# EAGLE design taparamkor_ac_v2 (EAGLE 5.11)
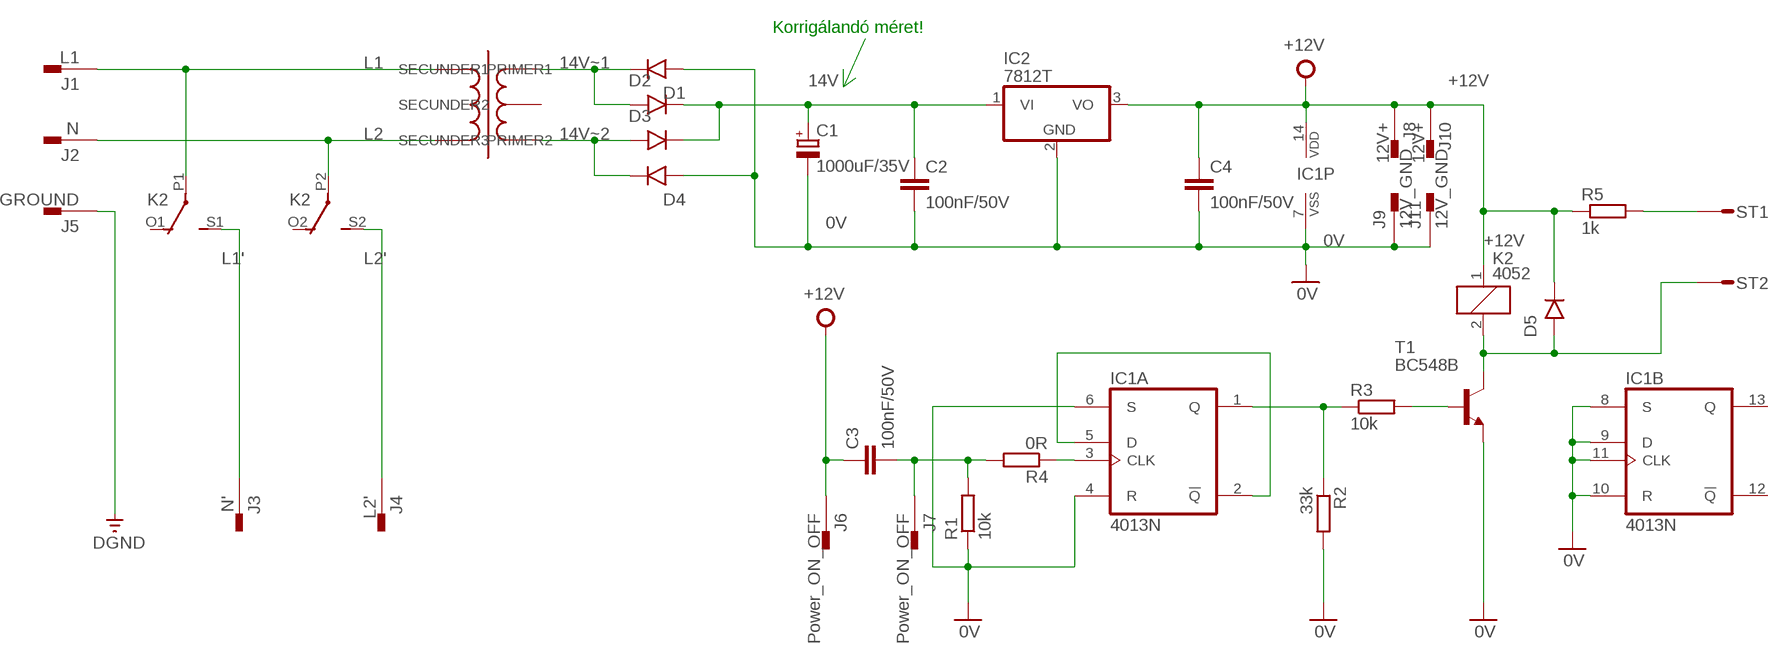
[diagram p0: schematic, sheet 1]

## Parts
C1  1000uF/35V  CPOL-EUE7.5-16  [E7,5-16]
C2  100nF/50V  C-EU025_050-025X075  [C025_050-025X075]
C3  100nF/50V  C-EU025_050-025X075  [C025_050-025X075]
C4  100nF/50V  C-EU025_050-025X075  [C025_050-025X075]
D1  1N4001  [DO41-10]
D2  1N4001  [DO41-10]
D3  1N4001  [DO41-10]
D4  1N4001  [DO41-10]
D5  1N4001  [DO41-10]
IC1  4013N  [DIL14]
IC2  7812T  [TO220H]
J1  L1  PIN2F061.100  [F061.100]
J2  N  PIN2F061.100  [F061.100]
J3  N'  PIN2F061.100  [F061.100]
J4  L2'  PIN2F061.100  [F061.100]
J5  GROUND  PIN2F061.100  [F061.100]
J6  Power_ON_OFF  PIN2F061.100  [F061.100]
J7  Power_ON_OFF  PIN2F061.100  [F061.100]
J8  12V+  PIN2F061.100  [F061.100]
J9  12V_GND  PIN2F061.100  [F061.100]
J10  12V+  PIN2F061.100  [F061.100]
J11  12V_GND  PIN2F061.100  [F061.100]
K2  4052  [F4052]
R1  10k  R-EU_0207/10  [0207/10]
R2  33k  R-EU_0207/10  [0207/10]
R3  10k  R-EU_0207/10  [0207/10]
R4  0R  R-EU_0207/10  [0207/10]
R5  1k  R-EU_0207/10  [0207/10]
ST1  ST2,8  [ST2,8]
ST2  ST2,8  [ST2,8]
T1  BC548B  BC548-NPN-TO92-CBE  [TO92-CBE]
U$1  Transformer  TRANSFORMER_12V_6W  [TRANSFORMER_12V_6W]

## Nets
0V: C1.- C2.2 C4.2 D1.A(ANODE) D4.A(ANODE) IC1.4(A:R) IC1.6(A:S) IC1.7(P:VSS) IC1.8(B:S) IC1.9(B:D) IC1.10(B:R) IC1.11(B:CLK) IC2.2(GND) J9.A1 J11.A1 R1.1 R2.2 T1.E
14V: C1.+ C2.1 D2.C(CATHODE) D3.C(CATHODE) IC2.1(VI)
14V~1: D1.C(CATHODE) D2.A(ANODE) U$1.SECUNDER1
14V~2: D3.A(ANODE) D4.C(CATHODE) U$1.SECUNDER3
+12V: C3.1 C4.1 D5.C(CATHODE) IC1.14(P:VDD) IC2.3(VO) J6.A1 J8.A1 J10.A1 K2.1 R5.1
DGND: J5.A1
L1: J1.A1 K2.P1(2:P) U$1.PRIMER1
L1': J3.A1 K2.S1(2:S)
L2: J2.A1 K2.P2(3:P) U$1.PRIMER2
L2': J4.A1 K2.S2(3:S)
N$1: D5.A(ANODE) K2.2 ST2.1(ST) T1.C
N$2: IC1.3(A:CLK) R4.1
N$5: R5.2 ST1.1(ST)
N$9: IC1.2(A:!Q) IC1.5(A:D)
N$12: C3.2 J7.A1 R1.2 R4.2
N$13: IC1.1(A:Q) R2.1 R3.1
N$15: R3.2 T1.B
Unconnected: IC1.12(B:!Q) IC1.13(B:Q) J1.A2(1.1) J2.A2(1.1) J3.A2(1.1) J4.A2(1.1) J5.A2(1.1) J6.A2(1.1) J7.A2(1.1) J8.A2(1.1) J9.A2(1.1) J10.A2(1.1) J11.A2(1.1) K2.O1(2:O) K2.O2(3:O) U$1.SECUNDER2

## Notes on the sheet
- Korrigálandó méret!

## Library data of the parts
C1 = Kameleon_2013:CPOL-EU: POLARIZED CAPACITOR, European symbol
C2-C4 = Kameleon_2013:C-EU: CAPACITOR, European symbol
D1-D5 = Kameleon_2013:1N4001: DIODE
IC1 = 40xx:4013: Dual D FLIP FLOP, set/reset
IC2 = linear:78*: Positive VOLTAGE REGULATOR Source: http://cache.national.com/ds/LM/LM78L05.pdf http://www.fairchildsemi.com/ds/LM/LM7805.pdf
J1-J11 = con-faston:PIN2: Flachstecker Typ Tyco/Electronics/AMP TAB, FASTON; OC_FARNELL: unknown; OC_NEWARK: unknown
K2 = relay:4052: RELAY 2 x switch, Finder; OC_FARNELL: unknown; OC_NEWARK: unknown
R1-R5 = Kameleon_2013:R-EU_: RESISTOR, European symbol
ST1 ST2 = con-rib:ST2,8: RIBBON CABLE CONNECTOR; OC_FARNELL: unknown; OC_NEWARK: unknown
T1 = transistor:*-NPN-: NPN Transistror BF959 corrected 2008.03.06
U$1 = Kameleon_2013:TRANSFORMER_12V_6W

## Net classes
0 default: width 0.635 mm
1 power: width 1.778 mm, clearance 2.032 mm

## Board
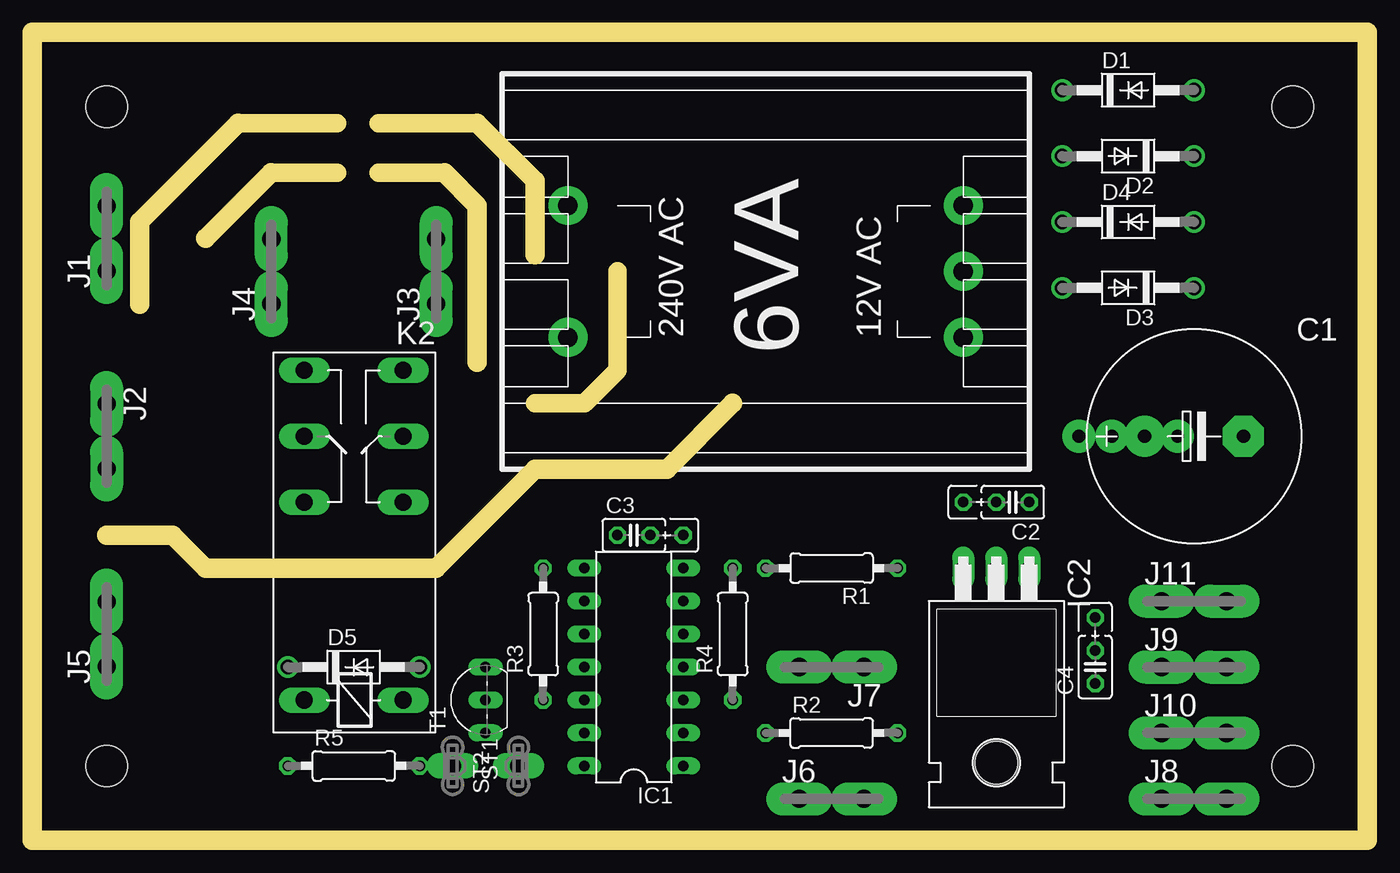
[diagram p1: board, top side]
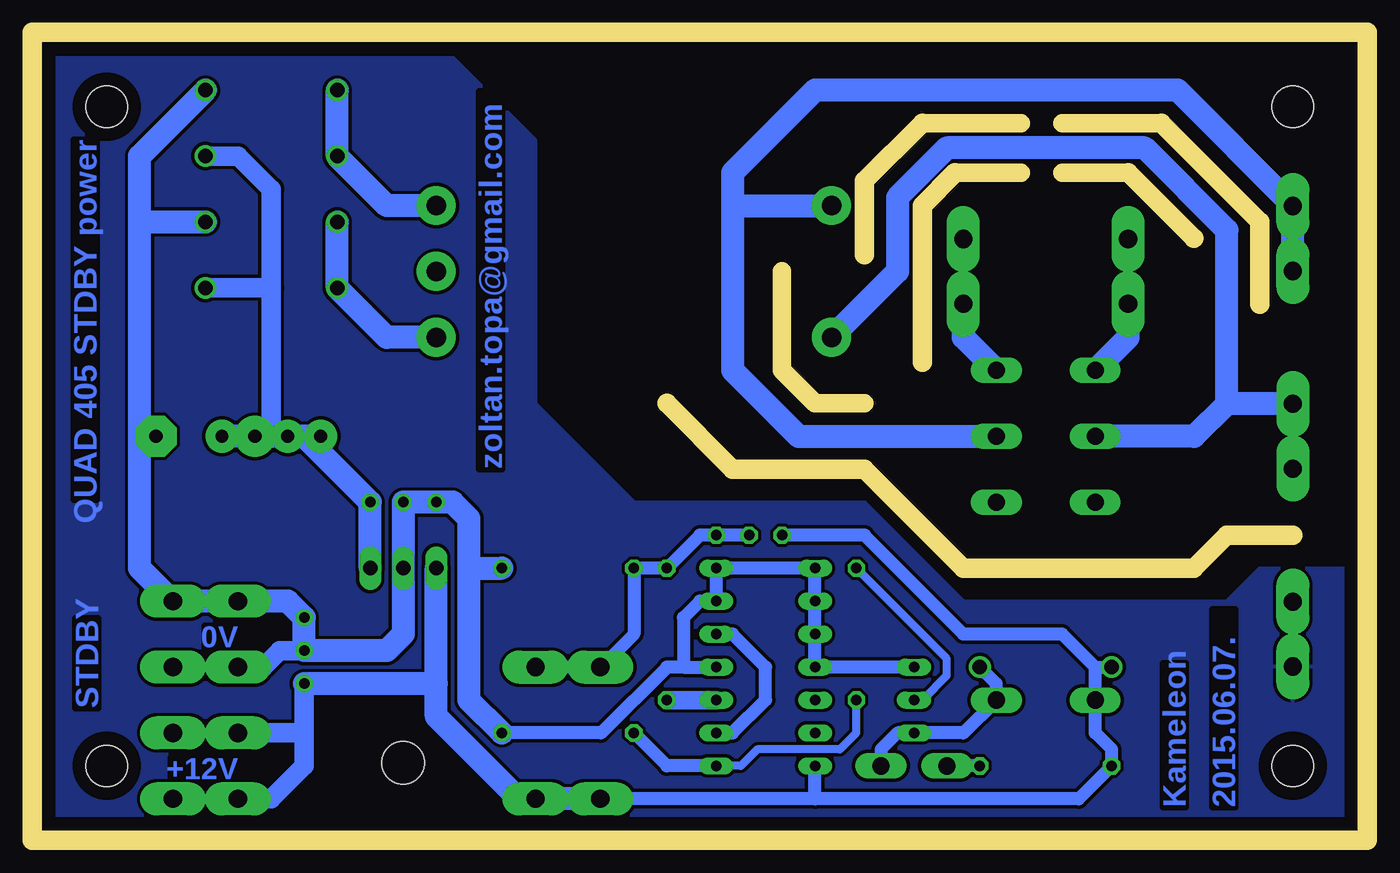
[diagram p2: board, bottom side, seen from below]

Size 102.87 x 62.23 mm. Coordinates in mm from the lower left corner, seen from the top.
Outline: 0,0 102.87,0 102.87,62.23 0,62.23 0,0
Copper layers (1*16): Top 0.035mm / dielectric 1.5mm / Bottom 0.035mm
Design rules "default": minimum track width 10mil, minimum drill 24mil, track to track 8mil, track to pad 8mil, pad to pad 8mil, via to via 8mil, smd to smd 8mil, copper to edge 40mil, drill to drill 8mil, minimum pad ring 10mil, minimum via ring 8mil, stop-mask expansion 4mil, vias tented up to drill 0mil, thermal gap 10mil
Holes 3.2 mm at 5.71,56.52 5.71,5.71 97.16,56.52 97.16,5.71
Milling: 24 lines

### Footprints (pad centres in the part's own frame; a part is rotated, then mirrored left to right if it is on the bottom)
E7,5-16 = drill 1.016 pad 3.15 round: + -3.81,0 | drill 1.016 pad 3.15 octagon: - 3.81,0
C025_050-025X075 = drill 0.813 octagon: 1 -1.27,0; 2 1.27,0; 3 3.81,0
DO41-10 = drill 1.118 round: A 5.08,0; C -5.08,0
DIL14 = drill 0.813 long: 1 -7.62,-3.81; 2 -5.08,-3.81; 3 -2.54,-3.81; 4 0,-3.81; 5 2.54,-3.81; 6 5.08,-3.81; 7 7.62,-3.81; 8 7.62,3.81; 9 5.08,3.81; 10 2.54,3.81; 11 0,3.81; 12 -2.54,3.81; 13 -5.08,3.81; 14 -7.62,3.81
TO220H = drill 1.118 long: 1 -2.54,-10.16; 2 0,-10.16; 3 2.54,-10.16 | hole 3.302: 0,4.826
F061.100 = drill 1.4 pad 2.54 long: A1 -2.5,0; A2 2.5,0
F4052 = drill 1.321 long: 1 -3.81,3.81; 2 -3.81,-3.81; O1 11.43,-3.81; O2 11.43,3.81; P1 16.51,-3.81; P2 16.51,3.81; S1 21.59,-3.81; S2 21.59,3.81
0207/10 = drill 0.813 octagon: 1 -5.08,0; 2 5.08,0
ST2,8 = drill 1.321 long: 1 0,0
TO92-CBE = drill 0.813 long: B 0,0; C -2.54,0; E 2.54,0
TRANSFORMER_12V_6W = drill 1.5 pad 3 round: PRIMER1 0,10.16; PRIMER2 0,0; SECUNDER1 30.48,10.16; SECUNDER2 30.48,5.08; SECUNDER3 30.48,0

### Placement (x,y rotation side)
C1  89.54,31.12 0 top
C2  75.57,26.04 180 top
C3  46.35,23.5 0 top
C4  81.92,13.33 90 top
D1  84.45,57.78 0 top
D2  84.45,52.7 180 top
D3  84.45,42.54 180 top
D4  84.45,47.62 0 top
D5  24.77,13.33 0 top
IC1  46.35,13.33 90 top
IC2  74.3,10.79 180 top
J1  5.71,46.35 90 top
J2  5.71,31.12 270 top
J3  31.12,43.81 90 top
J4  18.42,43.81 90 top
J5  5.71,15.88 90 top
J6  61.59,3.17 0 top
J7  61.59,13.33 180 top
J8  89.54,3.17 0 top
J9  89.54,13.33 0 top
J10  89.54,8.26 0 top
J11  89.54,18.42 0 top
K2  24.77,14.61 90 top
R1  61.59,20.96 180 top
R2  61.59,8.26 0 top
R3  39.37,15.88 90 top
R4  53.98,15.88 90 top
R5  24.77,5.71 0 top
ST1  32.38,5.71 270 top
ST2  37.46,5.71 90 top
T1  34.92,10.79 90 top
U$1  41.27,38.73 0 top

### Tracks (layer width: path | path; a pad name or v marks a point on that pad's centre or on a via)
0V
  Bottom 1.016: T1.E IC1.11 IC1.10 IC1.9 IC1.8 IC1.7 IC1.6 51.43,18.42 52.7,17.15 52.7,13.33 | 52.7,13.33 IC1.4 | 52.7,13.33 53.98,13.33 59.05,8.26 R2.2
  Bottom 1.422: 94.62,31.12 C1.-
  Bottom 1.5: J9.A1 85.09,13.33 83.82,14.61 C4.2
  Bottom 1.778: D1.A 94.62,52.7 94.62,47.62 | 94.62,47.62 D4.A | R2.2 69.22,10.79 69.22,20.96 | 69.22,20.96 69.22,24.77 70.48,26.04 C2.2 IC2.2 74.3,15.88 75.57,14.61 C4.2 81.92,17.15 83.19,18.42 J11.A1 92.08,18.42 94.62,20.96 94.62,31.12 94.62,47.62 | 69.22,20.96 R1.1
14V  (via drill 1 pad 2.54)
  Bottom 1.5: D2.C 87,52.7 84.45,50.16 84.45,42.54 | 84.45,42.54 D3.C | 84.45,31.12 84.45,42.54
  Bottom 1.778: IC2.1 C2.1 81.92,31.12 v83.19,31.12 84.45,31.12 C1.+
14V~1
  Bottom 1.778: D1.C D2.A 75.57,48.89 U$1.SECUNDER1
14V~2
  Bottom 1.778: U$1.SECUNDER3 75.57,38.73 D3.A D4.C
+12V
  Bottom 1.016: C3.1 38.73,23.5 31.12,15.88 23.5,15.88 20.96,13.33 | 42.54,3.17 J6.A1 | 42.54,3.17 IC1.14 | 20.96,13.33 K2.1 20.96,8.26 19.69,6.98 R5.1 22.23,3.17 42.54,3.17 | 20.96,13.33 D5.C
  Bottom 1.5: C4.1 81.92,8.26 | 81.92,8.26 81.92,5.71 84.45,3.17 J8.A1 | 81.92,8.26 J10.A1
  Bottom 1.778: 71.76,12.06 IC2.3 | 71.76,12.06 C4.1 | 71.76,12.06 71.76,9.53 65.41,3.17 J6.A1
DGND
  pour Bottom (isolate 0.254): 0.64,0.64 102.23,0.64 102.23,61.59 71.76,61.59 64.14,53.98 64.14,33.66 56.52,26.04 38.73,26.04 31.12,18.42 10.79,18.42 8.26,20.96 0.64,20.96
L1
  Bottom 1.778: J1.A1 5.71,48.89 14.61,57.78 42.54,57.78 48.89,51.43 48.89,48.89 | K2.P1 43.81,31.12 48.89,36.2 48.89,48.89 | 48.89,48.89 U$1.PRIMER1
L1'
  Bottom 1.778: J3.A1 31.12,38.73 K2.S1
L2
  Bottom 1.778: 10.79,33.61 10.79,46.99 17.15,53.34 32.38,53.34 36.2,49.53 36.2,43.81 U$1.PRIMER2 | J2.A1 10.79,33.61 | 10.79,33.61 13.33,31.12 K2.P2
L2'
  Bottom 1.778: J4.A1 18.42,38.73 K2.S2
N$1
  Bottom 1.016: ST2.1 37.46,6.98 36.2,8.26 T1.C 31.12,8.26 K2.2 28.58,12.06 D5.A
N$2
  Bottom 1.422: IC1.3 R4.1
N$4  (via drill 1 pad 2.54)
  Bottom 1.778: 80.65,31.12 v88.27,31.12
N$5
  Bottom 1.016: R5.2 ST1.1
N$6  (via drill 1 pad 2.54)
  other vias: 80.65,31.12
N$9
  Bottom 1.016: IC1.5 48.89,15.88 46.35,13.33 46.35,10.79 48.89,8.26 IC1.2
N$12
  Bottom 1.016: J7.A1 59.05,13.33 56.52,15.88 R1.2 R4.2 51.43,23.5 C3.2
N$13
  Bottom 0.61: R3.1 39.37,8.26 40.64,6.98 46.99,6.98 48.26,5.71 IC1.1
  Bottom 1.016: IC1.1 53.98,5.71 R2.1
N$15
  Bottom 0.61: R3.2 32.38,13.97 32.38,12.7 34.29,10.79 T1.B

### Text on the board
Bottom: QUAD 405 STDBY power | zoltan.topa@gmail.com | 0V | STDBY | +12V | 2015.06.07. | Kameleon
tValues: + LED -
Document: Transzformátor | L1 | N | L1 | N | Ground | 0V | Standby 12V | +12V | Bekapcsolást jelzö piros LED | Mikrokapcsoló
